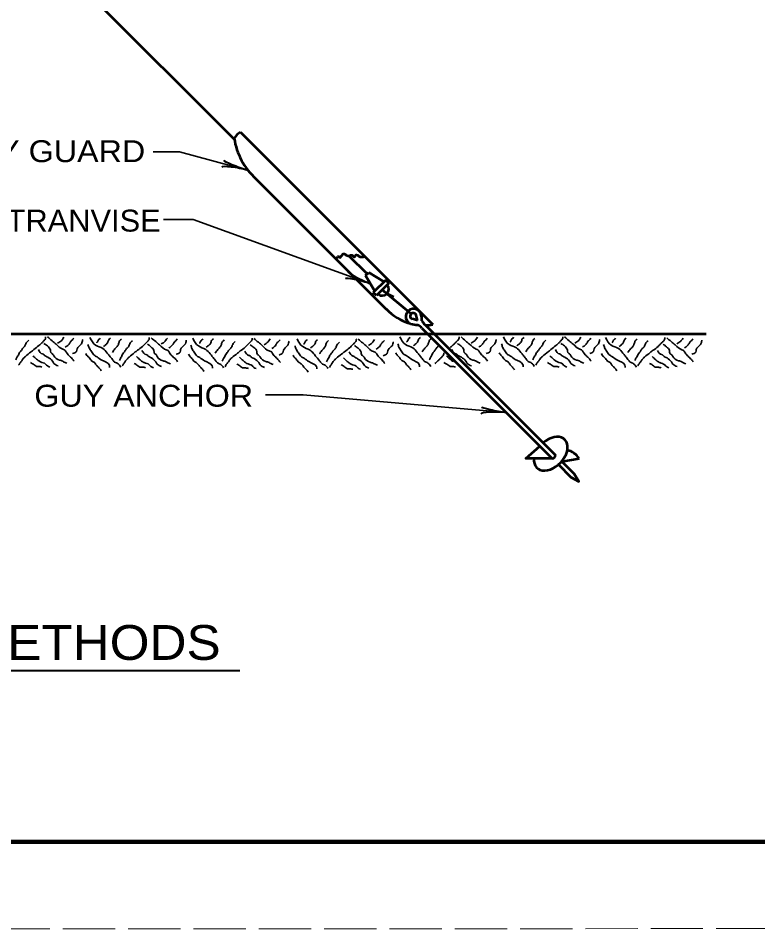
# Model space of a CAD drawing. Extents: x -1 to 679, y 0 to 440.
# Drawn here: x 405.2 to 490.2, y 0.2 to 104.8 of the extents above; entities that cross this region are included whole.
import ezdxf
from ezdxf.enums import TextEntityAlignment as Align

# ---------------------------------------------------------------- set-up
doc = ezdxf.new("R2010")
doc.units = 0
doc.linetypes.add('LONG_DASHED', pattern=[7.5, 6, -1.5])
doc.layers.add('1', color=7, linetype='Continuous', lineweight=53)
doc.layers.add('61', color=7, linetype='Continuous', lineweight=35)

msp = doc.modelspace()

# ---------------------------------------------------------------- linework, layer by layer
at = {"layer": '1'}
for p, q in [((385.459, 135.495), (430.039, 90.935)), ((430.739, 91.735), (452.839, 69.635)), ((432.519, 86.395), (447.499, 71.415)), ((443.159, 77.575), (445.299, 75.455)), ((445.119, 75.275), (445.479, 75.615)), ((447.259, 74.555), (445.479, 75.615)), ((446.179, 73.475), (445.119, 75.275)), ((447.439, 74.735), (445.999, 73.315)), ((447.779, 74.375), (446.359, 72.955)), ((447.779, 74.375), (447.439, 74.735)), ((446.359, 72.955), (445.999, 73.315)), ((450.339, 70.855), (447.039, 73.635)), ((447.579, 73.195), (448.319, 72.835)), ((451.079, 70.115), (450.499, 70.275)), ((451.079, 70.115), (450.919, 70.695)), ((451.959, 69.595), (466.939, 54.615)), ((295.899, 68.575), (484.219, 68.575)), ((467.659, 53.915), (469.639, 54.255)), ((467.659, 53.915), (469.079, 52.475))]:
    msp.add_line(p, q, dxfattribs=at)
at = {"layer": '1', "lineweight": 35}
for p, q in [((423.759, 89.475), (420.719, 89.475)), ((431.539, 87.375), (423.759, 89.475)), ((425.339, 81.715), (421.919, 81.715)), ((445.679, 74.315), (425.339, 81.715)), ((437.939, 61.575), (433.619, 61.575)), ((437.939, 61.575), (461.279, 59.535))]:
    msp.add_line(p, q, dxfattribs=at)
at = {"layer": '1', "lineweight": 40}
msp.add_line((355.637, 29.872), (430.689, 29.872), dxfattribs=at)
at = {"layer": '1'}
for points in [[(451.599, 69.215), (466.559, 54.255), (463.539, 54.255), (465.139, 55.655)], [(467.279, 53.535), (468.699, 52.115), (469.599, 51.595), (469.079, 52.475)]]:
    msp.add_lwpolyline(points, dxfattribs=at)
for centre, radius, start, end in [((431.432, 90.336), 1.56, 116.15616, 153.84384), ((437.742, 92.188), 7.798, 188.58388, 228.01714), ((447.025, 73.712), 0.759, 230.20411, 39.79589), ((451.797, 75.423), 5.875, 222.90975, 254.56822), ((450.636, 70.558), 0.894, 22.37581, 247.62419), ((450.584, 70.609), 0.353, 13.9871, 256.0129), ((449.276, 70.125), 2.319, 358.69833, 19.49446), ((451.165, 72.368), 2.777, 251.74116, 268.96028), ((450.466, 68.261), 1.48, 40.24577, 64.00426), ((452.925, 70.721), 1.48, 205.99574, 229.75423), ((451.797, 75.423), 5.875, 272.0576, 280.22035), ((466.55, 54.637), 0.387, 272.04039, 357.95961), ((467.86, 53.13), 2.105, 32.48706, 78.42981)]:
    msp.add_arc(centre, radius, start, end, dxfattribs=at)
at = {"layer": '1', "lineweight": 40}
for centre, major_axis, ratio, start_param, end_param in [((430.503, 87.88), (1.664, -0.629), 0.07063, 3.1407148, 5.41811), ((430.405, 87.398), (1.779, -0.314), 0.122415, 0.8963533, 3.1415927), ((444.695, 74.904), (-1.603, 0.772), 0.07063, 6.2823074, 8.5597026), ((444.695, 74.904), (-1.603, 0.772), 0.07063, 6.2823074, 8.5597026), ((444.554, 74.432), (1.745, -0.468), 0.122415, 0.8963533, 3.1415927), ((444.554, 74.432), (1.745, -0.468), 0.122415, 0.8963533, 3.1415927), ((460.172, 59.846), (1.748, -0.331), 0.07063, 3.1407148, 5.41811), ((460.159, 59.353), (1.807, 0), 0.122415, 0.8963533, 3.1415927)]:
    msp.add_ellipse(centre, major_axis=major_axis, ratio=ratio, start_param=start_param, end_param=end_param, dxfattribs=at)
at = {"layer": '1'}
msp.add_ellipse((466.394, 54.793), major_axis=(-1.612, -1.612), ratio=0.663245, start_param=5.5824837, end_param=10.8796755, dxfattribs=at)
msp.add_spline([(441.799, 77.135), (442.019, 77.455), (442.159, 77.355), (442.419, 77.615), (442.579, 77.755), (442.899, 77.615), (443.339, 77.555), (443.539, 77.595), (443.859, 77.415), (444.019, 77.615), (444.359, 77.495), (444.659, 77.415), (444.999, 77.475)], degree=3, dxfattribs=at)
at = {"layer": '1', "lineweight": 35}
for points in [[(408.379, 68.235), (408.379, 68.115), (408.319, 67.915), (408.179, 67.795), (408.059, 67.655), (407.799, 67.395), (407.599, 67.215), (407.019, 66.755), (406.699, 66.495), (406.059, 65.975), (405.799, 65.715), (405.679, 65.535), (405.479, 65.275), (405.279, 64.955)], [(408.599, 68.215), (409.119, 67.755), (409.579, 67.375), (410.339, 66.795), (410.539, 66.715), (410.739, 66.475), (411.059, 66.075), (411.439, 65.695), (411.639, 65.435)], [(409.759, 67.495), (410.219, 67.815), (410.319, 67.935), (410.479, 68.175)], [(410.639, 67.035), (410.999, 67.295), (411.219, 67.615), (411.279, 67.715), (411.419, 67.835), (411.599, 68.075)], [(413.459, 68.155), (414.119, 67.255), (414.959, 66.875), (415.459, 66.355), (415.719, 66.035), (416.039, 65.635), (416.299, 65.315), (416.699, 65.135), (417.019, 64.735)], [(414.639, 68.075), (414.539, 67.955), (414.499, 67.955), (414.439, 67.895), (414.279, 67.595), (414.239, 67.535)], [(415.819, 68.055), (415.639, 67.895), (415.559, 67.735), (415.499, 67.535), (415.379, 67.415), (415.299, 67.335), (415.019, 67.115)], [(420.279, 68.155), (420.279, 68.035), (420.199, 67.835), (420.079, 67.695), (419.959, 67.575), (419.699, 67.315), (419.499, 67.115), (418.919, 66.675), (418.599, 66.415), (417.959, 65.895), (417.699, 65.635), (417.559, 65.455), (417.379, 65.195), (417.179, 64.875)], [(420.499, 68.115), (421.019, 67.675), (421.459, 67.295), (422.239, 66.715), (422.439, 66.635), (422.619, 66.375), (422.939, 65.995), (423.339, 65.615), (423.539, 65.355)], [(421.659, 67.415), (422.119, 67.735), (422.199, 67.855), (422.359, 68.075)], [(425.279, 68.075), (425.919, 67.175), (426.759, 66.775), (427.279, 66.275), (427.539, 65.935), (427.859, 65.555), (428.119, 65.235), (428.499, 65.035), (428.819, 64.655)], [(432.079, 68.075), (432.079, 67.935), (432.019, 67.755), (431.879, 67.615), (431.759, 67.495), (431.499, 67.235), (431.299, 67.035), (430.719, 66.595), (430.399, 66.335), (429.759, 65.815), (429.499, 65.555), (429.379, 65.355), (429.179, 65.115), (428.979, 64.775)], [(432.299, 68.035), (432.819, 67.595), (433.279, 67.195), (434.039, 66.615), (434.239, 66.555), (434.439, 66.295), (434.759, 65.915), (435.139, 65.535), (435.339, 65.275)], [(449.059, 68.235), (449.699, 67.335), (450.539, 66.955), (451.059, 66.435), (451.319, 66.115), (451.639, 65.715), (451.899, 65.395), (452.279, 65.215), (452.619, 64.815)], [(450.219, 68.175), (450.119, 68.035), (450.099, 68.035), (450.039, 67.975), (449.879, 67.675), (449.839, 67.615)], [(451.419, 68.135), (451.219, 67.975), (451.159, 67.815), (451.099, 67.615), (450.959, 67.495), (450.899, 67.435), (450.619, 67.195)], [(452.679, 68.035), (452.479, 67.835), (452.359, 67.515), (452.199, 67.195), (451.839, 66.815), (451.699, 66.615), (451.639, 66.515)], [(455.859, 68.235), (455.859, 68.115), (455.799, 67.915), (455.679, 67.795), (455.539, 67.655), (455.279, 67.395), (455.099, 67.215), (454.839, 67.015)], [(456.099, 68.215), (456.599, 67.755), (457.059, 67.375), (457.839, 66.795), (458.019, 66.715), (458.219, 66.475), (458.539, 66.075), (458.939, 65.695), (459.119, 65.435)], [(457.259, 67.495), (457.699, 67.815), (457.799, 67.935), (457.959, 68.175)], [(458.119, 67.035), (458.479, 67.295), (458.699, 67.615), (458.759, 67.715), (458.899, 67.835), (459.099, 68.075)], [(460.959, 68.235), (461.599, 67.335), (462.439, 66.955), (462.959, 66.435), (463.219, 66.115), (463.539, 65.715), (463.799, 65.395), (464.179, 65.215), (464.499, 64.815)], [(462.119, 68.175), (462.019, 68.035), (461.979, 68.035), (461.919, 67.975), (461.759, 67.675), (461.739, 67.615)], [(463.319, 68.135), (463.119, 67.975), (463.059, 67.815), (462.979, 67.615), (462.859, 67.495), (462.799, 67.435), (462.499, 67.195)], [(464.559, 68.035), (464.379, 67.835), (464.239, 67.515), (464.079, 67.195), (463.719, 66.815), (463.599, 66.615), (463.539, 66.515)], [(467.759, 68.235), (467.759, 68.115), (467.699, 67.915), (467.559, 67.795), (467.439, 67.655), (467.179, 67.395), (466.979, 67.215), (466.399, 66.755), (466.079, 66.495), (465.439, 65.975), (465.179, 65.715), (465.059, 65.535), (464.859, 65.275), (464.659, 64.955)], [(467.979, 68.215), (468.499, 67.755), (468.959, 67.375), (469.719, 66.795), (469.919, 66.715), (470.119, 66.475), (470.439, 66.075), (470.819, 65.695), (471.019, 65.435)], [(469.139, 67.495), (469.599, 67.815), (469.699, 67.935), (469.859, 68.175)], [(470.019, 67.035), (470.379, 67.295), (470.599, 67.615), (470.659, 67.715), (470.799, 67.835), (470.979, 68.075)], [(472.679, 68.155), (473.319, 67.255), (474.159, 66.875), (474.679, 66.355), (474.939, 66.035), (475.259, 65.635), (475.519, 65.315), (475.899, 65.135), (476.219, 64.735)], [(473.839, 68.075), (473.739, 67.955), (473.719, 67.955), (473.639, 67.895), (473.479, 67.595), (473.459, 67.535)], [(475.039, 68.055), (474.839, 67.895), (474.779, 67.735), (474.719, 67.535), (474.579, 67.415), (474.519, 67.335), (474.239, 67.115)], [(479.479, 68.155), (479.479, 68.035), (479.419, 67.835), (479.299, 67.695), (479.159, 67.575), (478.899, 67.315), (478.719, 67.115), (478.139, 66.675), (477.799, 66.415), (477.159, 65.895), (476.899, 65.635), (476.779, 65.455), (476.579, 65.195), (476.399, 64.875)], [(479.719, 68.115), (480.219, 67.675), (480.679, 67.295), (481.459, 66.715), (481.639, 66.635), (481.839, 66.375), (482.159, 65.995), (482.539, 65.615), (482.739, 65.355)], [(480.879, 67.415), (481.319, 67.735), (481.419, 67.855), (481.579, 68.075)], [(406.439, 67.835), (406.159, 67.515), (405.999, 67.175), (405.739, 66.875), (405.539, 66.595), (405.339, 66.355), (405.259, 66.135), (405.119, 65.915), (404.959, 65.595)], [(408.179, 67.455), (408.379, 67.335), (408.579, 67.175), (408.919, 66.715), (408.959, 66.435), (409.219, 66.195), (409.319, 66.035), (409.959, 65.555), (410.339, 65.435), (410.439, 65.355), (410.799, 65.195)], [(411.479, 66.295), (411.919, 66.555), (411.999, 66.835), (412.419, 67.355), (412.539, 67.515), (412.599, 67.775), (412.639, 67.915)], [(413.239, 67.335), (413.379, 66.955), (413.639, 66.535), (413.959, 66.115), (414.279, 65.915), (414.819, 65.535), (415.699, 64.955), (415.719, 64.695)], [(417.079, 67.955), (416.879, 67.755), (416.759, 67.435), (416.599, 67.115), (416.239, 66.735), (416.119, 66.535), (416.039, 66.435)], [(418.339, 67.755), (418.039, 67.435), (417.879, 67.075), (417.619, 66.795), (417.439, 66.495), (417.239, 66.275), (417.139, 66.055), (417.019, 65.835), (416.859, 65.495)], [(420.079, 67.375), (420.279, 67.255), (420.459, 67.075), (420.819, 66.635), (420.859, 66.335), (421.119, 66.115), (421.199, 65.955), (421.859, 65.475), (422.239, 65.335), (422.339, 65.275), (422.699, 65.115)], [(422.539, 66.955), (422.879, 67.215), (423.119, 67.535), (423.179, 67.635), (423.299, 67.755), (423.499, 67.995)], [(423.359, 66.215), (423.819, 66.475), (423.879, 66.755), (424.299, 67.275), (424.439, 67.435), (424.499, 67.695), (424.519, 67.835)], [(425.059, 67.255), (425.179, 66.875), (425.439, 66.455), (425.759, 66.035), (426.079, 65.835), (426.639, 65.455), (427.499, 64.875), (427.539, 64.615)], [(426.439, 67.995), (426.339, 67.875), (426.319, 67.875), (426.239, 67.815), (426.079, 67.515), (426.059, 67.455)], [(427.639, 67.975), (427.439, 67.815), (427.379, 67.655), (427.319, 67.455), (427.179, 67.315), (427.119, 67.255), (426.819, 67.035)], [(428.899, 67.875), (428.699, 67.675), (428.559, 67.355), (428.399, 67.035), (428.059, 66.655), (427.919, 66.455), (427.859, 66.355)], [(430.139, 67.675), (429.859, 67.355), (429.699, 66.995), (429.439, 66.715), (429.239, 66.415), (429.059, 66.195), (428.959, 65.975), (428.819, 65.735), (428.659, 65.415)], [(431.879, 67.295), (432.079, 67.155), (432.279, 66.995), (432.639, 66.555), (432.659, 66.255), (432.919, 66.035), (433.019, 65.875), (433.659, 65.395), (434.039, 65.255), (434.139, 65.195), (434.499, 65.035)], [(433.459, 67.315), (433.919, 67.655), (434.019, 67.775), (434.179, 67.995)], [(434.339, 66.875), (434.699, 67.135), (434.919, 67.455), (434.979, 67.555), (435.119, 67.675), (435.299, 67.895)], [(435.179, 66.135), (435.619, 66.395), (435.699, 66.675), (436.119, 67.195), (436.239, 67.355), (436.299, 67.615), (436.339, 67.735)], [(437.019, 67.175), (437.159, 66.795), (437.419, 66.375), (437.739, 65.955), (438.059, 65.755), (438.599, 65.375), (439.479, 64.795), (439.519, 64.535)], [(437.259, 67.995), (437.899, 67.095), (438.739, 66.695), (439.259, 66.175), (439.519, 65.855), (439.839, 65.475), (440.099, 65.155), (440.479, 64.955), (440.799, 64.575)], [(438.419, 67.915), (438.319, 67.795), (438.279, 67.795), (438.219, 67.715), (438.059, 67.435), (438.019, 67.375)], [(439.599, 67.895), (439.419, 67.715), (439.359, 67.555), (439.279, 67.375), (439.159, 67.235), (439.099, 67.175), (438.799, 66.955)], [(440.859, 67.795), (440.679, 67.595), (440.539, 67.275), (440.379, 66.955), (440.019, 66.555), (439.899, 66.375), (439.839, 66.275)], [(442.119, 67.595), (441.839, 67.275), (441.679, 66.915), (441.419, 66.635), (441.219, 66.335), (441.019, 66.115), (440.939, 65.895), (440.799, 65.655), (440.639, 65.335)], [(444.059, 67.995), (444.059, 67.855), (443.999, 67.675), (443.859, 67.535), (443.739, 67.415), (443.479, 67.155), (443.279, 66.955), (442.699, 66.515), (442.379, 66.255), (441.739, 65.735), (441.479, 65.475), (441.339, 65.275), (441.159, 65.015), (440.959, 64.695)], [(443.859, 67.215), (444.059, 67.075), (444.259, 66.915), (444.599, 66.475), (444.639, 66.175), (444.899, 65.955), (444.999, 65.795), (445.639, 65.315), (446.019, 65.175), (446.119, 65.115), (446.479, 64.955)], [(444.279, 67.955), (444.799, 67.515), (445.259, 67.115), (446.019, 66.535), (446.219, 66.475), (446.419, 66.215), (446.739, 65.835), (447.119, 65.435), (447.319, 65.175)], [(445.439, 67.235), (445.899, 67.555), (445.999, 67.695), (446.159, 67.915)], [(446.319, 66.795), (446.679, 67.055), (446.899, 67.375), (446.959, 67.475), (447.079, 67.595), (447.279, 67.815)], [(447.159, 66.055), (447.599, 66.315), (447.659, 66.595), (448.079, 67.115), (448.219, 67.275), (448.279, 67.535), (448.319, 67.655)], [(448.839, 67.435), (448.959, 67.035), (449.219, 66.615), (449.539, 66.195), (449.879, 66.015), (450.419, 65.615), (451.279, 65.035), (451.319, 64.775)], [(453.439, 67.115), (453.219, 66.875), (453.039, 66.595), (452.839, 66.355), (452.739, 66.135), (452.619, 65.915), (452.439, 65.595)], [(455.679, 67.455), (455.859, 67.335), (456.059, 67.175), (456.419, 66.715), (456.439, 66.435), (456.699, 66.195), (456.799, 66.035), (457.439, 65.555), (457.839, 65.435), (457.939, 65.355), (458.279, 65.195)], [(458.959, 66.295), (459.419, 66.555), (459.479, 66.835), (459.899, 67.355), (460.019, 67.515), (460.099, 67.775), (460.119, 67.915)], [(460.739, 67.435), (460.859, 67.035), (461.119, 66.615), (461.439, 66.195), (461.759, 66.015), (462.319, 65.615), (463.179, 65.035), (463.219, 64.775)], [(465.819, 67.835), (465.539, 67.515), (465.379, 67.175), (465.119, 66.875), (464.919, 66.595), (464.719, 66.355), (464.639, 66.135), (464.499, 65.915), (464.339, 65.595)], [(467.559, 67.455), (467.759, 67.335), (467.959, 67.175), (468.299, 66.715), (468.339, 66.435), (468.599, 66.195), (468.699, 66.035), (469.339, 65.555), (469.719, 65.435), (469.819, 65.355), (470.179, 65.195)], [(470.859, 66.295), (471.299, 66.555), (471.379, 66.835), (471.799, 67.355), (471.919, 67.515), (471.979, 67.775), (472.019, 67.915)], [(472.459, 67.335), (472.579, 66.955), (472.839, 66.535), (473.159, 66.115), (473.479, 65.915), (474.039, 65.535), (474.899, 64.955), (474.939, 64.695)], [(476.299, 67.955), (476.099, 67.755), (475.979, 67.435), (475.819, 67.115), (475.459, 66.735), (475.319, 66.535), (475.259, 66.435)], [(477.559, 67.755), (477.259, 67.435), (477.099, 67.075), (476.839, 66.795), (476.639, 66.495), (476.459, 66.275), (476.359, 66.055), (476.219, 65.835), (476.059, 65.495)], [(479.299, 67.375), (479.479, 67.255), (479.679, 67.075), (480.039, 66.635), (480.059, 66.335), (480.319, 66.115), (480.419, 65.955), (481.059, 65.475), (481.459, 65.335), (481.539, 65.275), (481.899, 65.115)], [(481.739, 66.955), (482.099, 67.215), (482.319, 67.535), (482.379, 67.635), (482.519, 67.755), (482.719, 67.995)], [(482.579, 66.215), (483.039, 66.475), (483.099, 66.755), (483.519, 67.275), (483.639, 67.435), (483.719, 67.695), (483.739, 67.835)], [(406.939, 66.035), (407.339, 65.655), (407.519, 65.515), (407.799, 65.335), (408.379, 65.095), (408.579, 64.875), (408.859, 64.755)], [(407.539, 66.755), (408.019, 66.255), (408.119, 66.235), (408.219, 66.135), (408.639, 65.875), (409.159, 65.435), (409.319, 65.175), (409.799, 64.875)], [(412.979, 66.315), (413.119, 66.075), (413.379, 65.835), (413.699, 65.435), (413.979, 65.255), (414.239, 64.915), (414.499, 64.675), (414.759, 64.335)], [(418.819, 65.955), (419.239, 65.575), (419.399, 65.435), (419.699, 65.255), (420.279, 65.015), (420.459, 64.795), (420.759, 64.675)], [(419.439, 66.655), (419.919, 66.175), (420.019, 66.155), (420.119, 66.055), (420.539, 65.795), (421.039, 65.335), (421.199, 65.095), (421.699, 64.795)], [(424.799, 66.235), (424.919, 65.995), (425.179, 65.735), (425.499, 65.355), (425.799, 65.155), (426.059, 64.835), (426.319, 64.575), (426.559, 64.255)], [(431.239, 66.575), (431.719, 66.095), (431.819, 66.075), (431.919, 65.975), (432.339, 65.715), (432.859, 65.255), (433.019, 64.995), (433.499, 64.715)], [(436.779, 66.135), (436.899, 65.915), (437.159, 65.655), (437.479, 65.275), (437.779, 65.075), (438.019, 64.755), (438.279, 64.495), (438.539, 64.175)], [(443.219, 66.495), (443.699, 66.015), (443.799, 65.975), (443.899, 65.895), (444.319, 65.635), (444.839, 65.175), (444.999, 64.915), (445.479, 64.635)], [(448.579, 66.395), (448.699, 66.175), (448.959, 65.915), (449.279, 65.515), (449.579, 65.335), (449.839, 65.015), (450.099, 64.755), (450.359, 64.435)], [(454.099, 66.395), (454.099, 66.255), (454.039, 66.075), (453.899, 65.935), (453.779, 65.815), (453.519, 65.555), (453.319, 65.355), (453.079, 65.155)], [(454.419, 66.035), (454.839, 65.655), (454.999, 65.515), (455.219, 65.375)], [(455.019, 66.755), (455.519, 66.255), (455.599, 66.235), (455.699, 66.135), (456.119, 65.875), (456.639, 65.435), (456.799, 65.175), (457.279, 64.875)], [(460.479, 66.395), (460.599, 66.175), (460.859, 65.915), (461.179, 65.515), (461.479, 65.335), (461.739, 65.015), (461.979, 64.755), (462.239, 64.435)], [(466.299, 66.035), (466.719, 65.655), (466.879, 65.515), (467.179, 65.335), (467.759, 65.095), (467.959, 64.875), (468.239, 64.755)], [(466.919, 66.755), (467.399, 66.255), (467.499, 66.235), (467.599, 66.135), (468.019, 65.875), (468.539, 65.435), (468.699, 65.175), (469.179, 64.875)], [(472.199, 66.315), (472.319, 66.075), (472.579, 65.835), (472.899, 65.435), (473.199, 65.255), (473.459, 64.915), (473.719, 64.675), (473.979, 64.335)], [(478.039, 65.955), (478.459, 65.575), (478.619, 65.435), (478.899, 65.255), (479.479, 65.015), (479.679, 64.795), (479.959, 64.675)], [(478.639, 66.655), (479.139, 66.175), (479.219, 66.155), (479.319, 66.055), (479.739, 65.795), (480.259, 65.335), (480.419, 65.095), (480.899, 64.795)], [(406.639, 65.255), (406.859, 65.135), (407.279, 64.855), (407.339, 64.815), (407.539, 64.815), (407.959, 64.755)], [(418.539, 65.175), (418.759, 65.055), (419.179, 64.755), (419.239, 64.735), (419.439, 64.735), (419.859, 64.675)], [(430.339, 65.095), (430.559, 64.975), (430.979, 64.675), (431.059, 64.655), (431.239, 64.655), (431.659, 64.575)], [(430.639, 65.875), (431.059, 65.495), (431.219, 65.355), (431.499, 65.155), (432.079, 64.935), (432.279, 64.715), (432.559, 64.575)], [(442.319, 65.015), (442.539, 64.895), (442.959, 64.595), (443.019, 64.555), (443.219, 64.555), (443.639, 64.495)], [(442.599, 65.795), (443.019, 65.395), (443.179, 65.275), (443.479, 65.075), (444.059, 64.855), (444.259, 64.635), (444.539, 64.495)], [(454.119, 65.255), (454.359, 65.135), (454.779, 64.855), (454.839, 64.815), (455.019, 64.815), (455.439, 64.755)], [(466.019, 65.255), (466.239, 65.135), (466.659, 64.855), (466.719, 64.815), (466.919, 64.815), (467.339, 64.755)], [(477.739, 65.175), (477.979, 65.055), (478.379, 64.755), (478.459, 64.735), (478.639, 64.735), (479.059, 64.675)]]:
    msp.add_spline(points, degree=3, dxfattribs=at)
at = {"layer": '61', "lineweight": 158}
msp.add_line((667.931, 10.202), (28.871, 10.222), dxfattribs=at)
at = {"layer": '61', "linetype": 'LONG_DASHED', "lineweight": 13}
msp.add_line((678.871, 0.222), (-1.189, 0.202), dxfattribs=at)

# ---------------------------------------------------------------- texts
at = {"layer": '1', "width": 1.1}
for s, p in [('GUY GUARD', (408.591, 88.295)), ('GUY ANCHOR', (419.64, 60.195))]:
    msp.add_text(s, height=2.52, dxfattribs=at).set_placement(p, align=Align.CENTER)
at = {"layer": '1'}
for s, height, width, p in [('STRANVISE', 2.52, 1.05, (401.539, 80.315)), ('POLE GUYING METHODS', 4, 1.1, (356.884, 31.102))]:
    msp.add_text(s, height=height, dxfattribs=dict(at, width=width)).set_placement(p)

doc.saveas('drawing.dxf')
